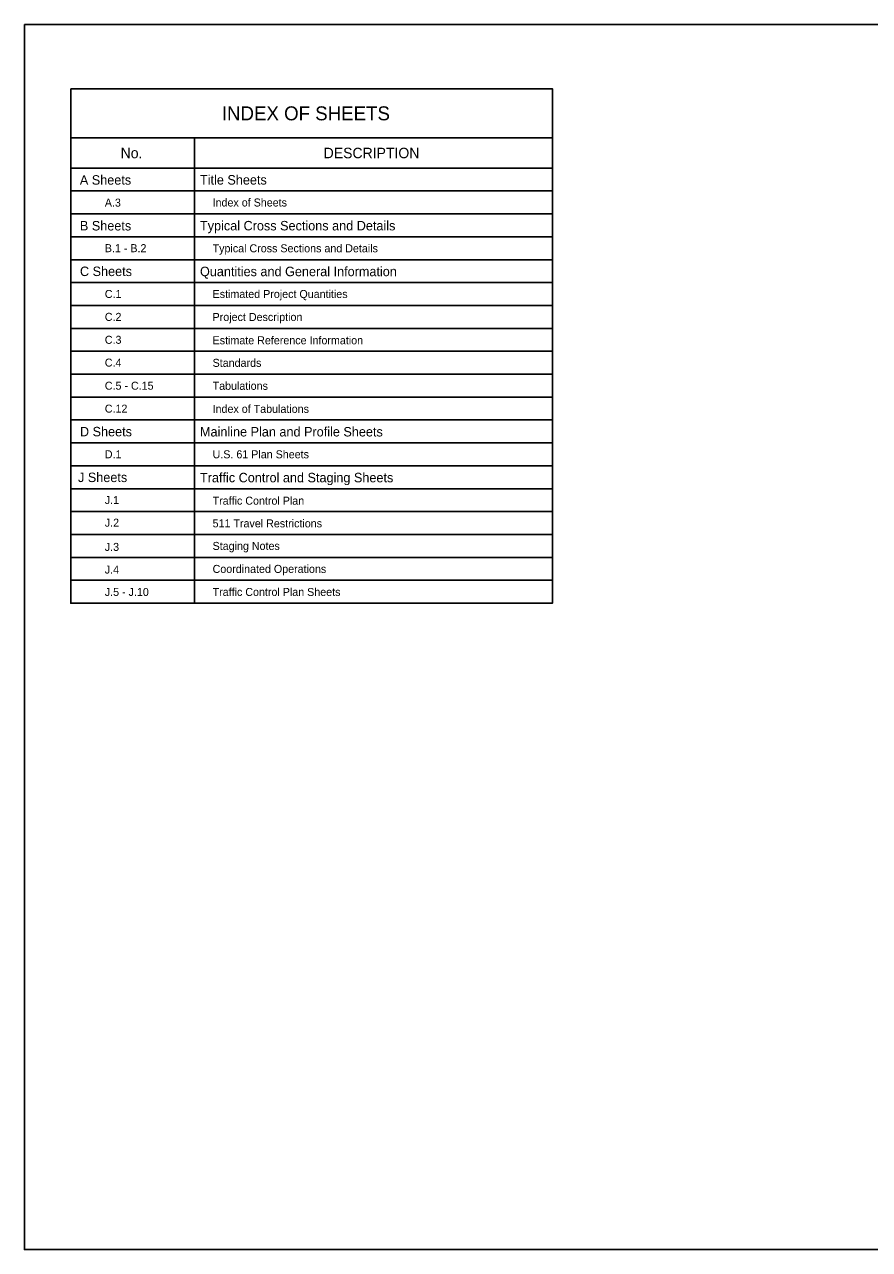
# Model space of a CAD drawing. Extents: x 10133 to 81668, y 7924 to 11018.
# Drawn here: x 10133 to 11526, y 7924 to 9944 of the extents above; entities that cross this region are included whole.
import ezdxf

# ---------------------------------------------------------------- set-up
doc = ezdxf.new("R2010")
doc.units = 0
doc.layers.add('SheetBorder', color=7, linetype='Continuous')

msp = doc.modelspace()

# ---------------------------------------------------------------- linework, layer by layer
at = {"layer": 'SheetBorder'}
for p, q in [((11003.2, 9757), (10208.8, 9757)), ((10412.8, 9757), (10412.8, 8989.8)), ((11003.2, 9707.3), (10208.8, 9707.3)), ((11003.2, 9669.5), (10208.8, 9669.5)), ((11003.2, 9631.8), (10208.8, 9631.8)), ((11003.2, 9594), (10208.8, 9594)), ((11003.2, 9556.2), (10208.8, 9556.2)), ((11003.2, 9518.5), (10208.8, 9518.5)), ((11003.2, 9480.7), (10208.8, 9480.7)), ((11003.2, 9442.9), (10208.8, 9442.9)), ((11003.2, 9405.2), (10208.8, 9405.2)), ((11003.2, 9367.4), (10208.8, 9367.4)), ((11003.2, 9329.6), (10208.8, 9329.6)), ((11003.2, 9291.9), (10208.8, 9291.9)), ((11003.2, 9254.1), (10208.8, 9254.1)), ((11003.2, 9216.4), (10208.8, 9216.4)), ((11003.2, 9178.6), (10208.8, 9178.6)), ((11003.2, 9140.8), (10208.8, 9140.8)), ((11003.2, 9103.1), (10208.8, 9103.1)), ((11003.2, 9065.3), (10208.8, 9065.3)), ((11003.2, 9027.5), (10208.8, 9027.5))]:
    msp.add_line(p, q, dxfattribs=at)
for points in [[(10132.5, 9944), (13267.5, 9944), (13267.5, 7924), (10132.5, 7924)], [(10208.8, 9838.1), (11003.2, 9838.1), (11003.2, 8989.8), (10208.8, 8989.8)]]:
    msp.add_lwpolyline(points, close=True, dxfattribs=at)

# ---------------------------------------------------------------- texts
for s, height, p in [('INDEX OF SHEETS', 23.04, (10458, 9786)), ('No.', 17.28, (10291.1, 9723.5)), ('DESCRIPTION', 17.28, (10626, 9723.5)), ('A Sheets', 15.6, (10223.8, 9679.9)), ('Title Sheets', 15.6, (10422, 9680.1)), ('A.3', 13.2, (10265, 9643.7)), ('Index of Sheets', 13.2, (10442.8, 9643.9)), ('B Sheets', 15.6, (10223.9, 9604.4)), ('Typical Cross Sections and Details', 15.6, (10422, 9604.5)), ('B.1 - B.2', 13.2, (10265, 9568.6)), ('Typical Cross Sections and Details', 13.2, (10442.8, 9568.4)), ('C Sheets', 15.6, (10224, 9529.2)), ('Quantities and General Information', 15.6, (10422, 9529)), ('C.1', 13.2, (10265, 9493.1)), ('Estimated Project Quantities', 13.2, (10442.8, 9493)), ('C.2', 13.2, (10265, 9455.3)), ('Project Description', 13.2, (10442.8, 9455.1)), ('C.3', 13.2, (10265, 9417.5)), ('Estimate Reference Information', 13.2, (10442.8, 9416.7)), ('C.4', 13.2, (10265, 9379.9)), ('Standards', 13.2, (10442.8, 9379.5)), ('C.5 - C.15', 13.2, (10265, 9341.8)), ('Tabulations', 13.2, (10442.8, 9341.6)), ('C.12', 13.2, (10265, 9304)), ('Index of Tabulations', 13.2, (10442.8, 9303.6)), ('D Sheets', 15.6, (10224, 9264.9)), ('Mainline Plan and Profile Sheets', 15.6, (10422, 9264.7)), ('D.1', 13.2, (10265, 9228.7)), ('U.S. 61 Plan Sheets', 13.2, (10442.8, 9228.7)), ('J Sheets', 15.6, (10220.8, 9189.5)), ('Traffic Control and Staging Sheets', 15.6, (10422, 9189.1)), ('J.1', 13.2, (10265, 9153.3)), ('Traffic Control Plan', 13.2, (10442.8, 9152.2)), ('J.2', 13.2, (10265, 9115.9)), ('511 Travel Restrictions', 13.2, (10442.8, 9114.8)), ('Staging Notes', 13.2, (10442.8, 9077.6)), ('J.3', 13.2, (10265, 9076)), ('J.4', 13.2, (10265, 9038.6)), ('Coordinated Operations', 13.2, (10442.8, 9039.7)), ('J.5 - J.10', 13.2, (10265, 9001.7)), ('Traffic Control Plan Sheets', 13.2, (10442.8, 9001.7))]:
    msp.add_text(s, height=height, dxfattribs=at).set_placement(p)

doc.saveas('drawing.dxf')
